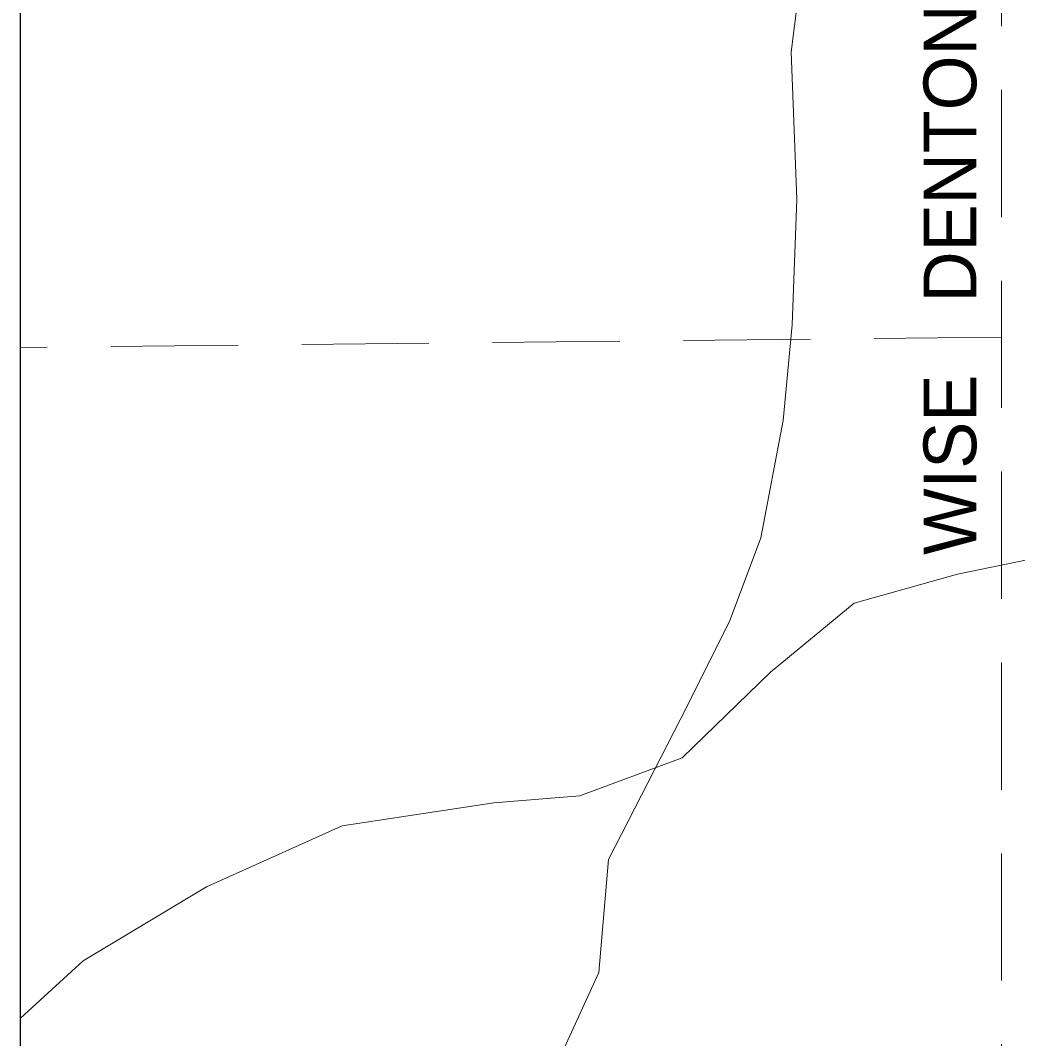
# Model space of a CAD drawing. Extents: x 2363323 to 2367082, y 6956018 to 6980837.
# Drawn here: x 2365769 to 2365865.4, y 6956731.2 to 6956829.6 of the extents above; entities that cross this region are included whole.
import ezdxf

# ---------------------------------------------------------------- set-up
doc = ezdxf.new("R2010")
doc.units = 0
doc.header["$LTSCALE"] = 4.1
doc.linetypes.add('MEDIUM_DASHED', pattern=[4.5, 3, -1.5])
doc.layers.add('62', color=7, linetype='Continuous', lineweight=13)
doc.layers.add('63', color=7, linetype='Continuous', lineweight=13)

msp = doc.modelspace()

# ---------------------------------------------------------------- linework, layer by layer
at = {"layer": '62', "lineweight": 25}
msp.add_line((2365769.011, 6956632.956), (2365769.009, 6957082.548), dxfattribs=at)
at = {"layer": '62', "linetype": 'MEDIUM_DASHED'}
for p, q in [((2365863.857, 6957081.22), (2365863.856, 6956632.956)), ((2365863.857, 6956798.998), (2365769.011, 6956798.01))]:
    msp.add_line(p, q, dxfattribs=at)
at = {"layer": '62'}
for points in [[(2365824.322, 6956696.614), (2365819.391, 6956707.214), (2365817.547, 6956721.502), (2365824.929, 6956737.592), (2365825.873, 6956748.528), (2365832.872, 6956762.142), (2365837.575, 6956771.524), (2365840.589, 6956779.605), (2365842.749, 6956790.966), (2365843.625, 6956800.191), (2365844.075, 6956812.344), (2365843.535, 6956826.564), (2365845.831, 6956844.68), (2365846.641, 6956856.47), (2365848.238, 6956869.904), (2365854.813, 6956884.734), (2365861.403, 6956898.816), (2365868.063, 6956911.69), (2365879.313, 6956926.316), (2365886.449, 6956936.15), (2365893.964, 6956948.19), (2365900.828, 6956955.074)], [(2365769.009, 6956733.18), (2365775.085, 6956738.739), (2365786.99, 6956745.897), (2365800.13, 6956751.766), (2365814.777, 6956754.018), (2365823.083, 6956754.693), (2365833.005, 6956758.36), (2365841.533, 6956766.64), (2365849.635, 6956773.302), (2365859.602, 6956776.114), (2365872.001, 6956778.658)]]:
    msp.add_lwpolyline(points, dxfattribs=at)
at = {"layer": '63', "lineweight": 25}
msp.add_line((2365769.011, 6956632.956), (2365769.009, 6957082.548), dxfattribs=at)
at = {"layer": '63', "linetype": 'MEDIUM_DASHED'}
for p, q in [((2365863.857, 6957081.22), (2365863.856, 6956632.956)), ((2365863.857, 6956798.998), (2365769.011, 6956798.01))]:
    msp.add_line(p, q, dxfattribs=at)
at = {"layer": '63'}
for points in [[(2365824.322, 6956696.614), (2365819.391, 6956707.214), (2365817.547, 6956721.502), (2365824.929, 6956737.592), (2365825.873, 6956748.528), (2365832.872, 6956762.142), (2365837.575, 6956771.524), (2365840.589, 6956779.605), (2365842.749, 6956790.966), (2365843.625, 6956800.191), (2365844.075, 6956812.344), (2365843.535, 6956826.564), (2365845.831, 6956844.68), (2365846.641, 6956856.47), (2365848.238, 6956869.904), (2365854.813, 6956884.734), (2365861.403, 6956898.816), (2365868.063, 6956911.69), (2365879.313, 6956926.316), (2365886.449, 6956936.15), (2365893.964, 6956948.19), (2365900.828, 6956955.074)], [(2365769.009, 6956733.18), (2365775.085, 6956738.739), (2365786.99, 6956745.897), (2365800.13, 6956751.766), (2365814.777, 6956754.018), (2365823.083, 6956754.693), (2365833.005, 6956758.36), (2365841.533, 6956766.64), (2365849.635, 6956773.302), (2365859.602, 6956776.114), (2365872.001, 6956778.658)]]:
    msp.add_lwpolyline(points, dxfattribs=at)

# ---------------------------------------------------------------- texts
at = {"layer": '62'}
for s, p in [('DENTON', (2365861.426, 6956802.377)), ('WISE', (2365861.425, 6956777.962))]:
    msp.add_text(s, height=5.099, rotation=90, dxfattribs=at).set_placement(p)
at = {"layer": '63'}
for s, p in [('DENTON', (2365861.426, 6956802.377)), ('WISE', (2365861.425, 6956777.962))]:
    msp.add_text(s, height=5.099, rotation=90, dxfattribs=at).set_placement(p)

doc.saveas('drawing.dxf')
